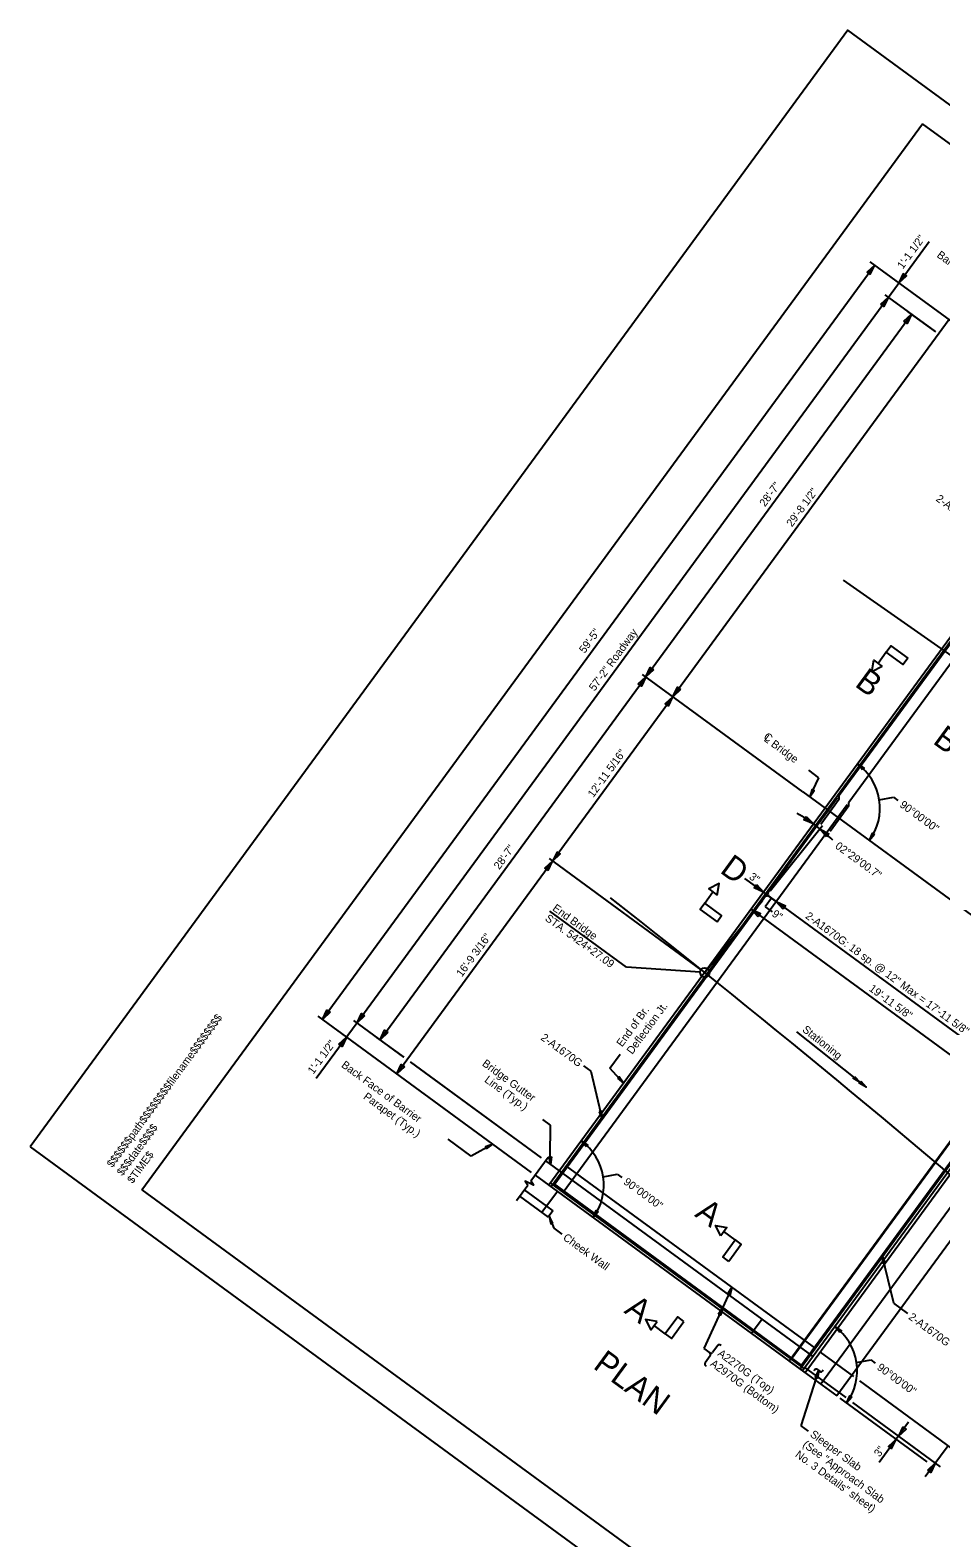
# Model space of a CAD drawing. Extents: x 1970731 to 1970899, y 796145 to 796301.
# Drawn here: x 1970731.3 to 1970789.2, y 796205.4 to 796301.3 of the extents above; entities that cross this region are included whole.
import ezdxf

# ---------------------------------------------------------------- set-up
doc = ezdxf.new("R2010")
doc.units = 0
for name, color, linetype in [('BR_AUTO DIMENSION', 7, 'Continuous'), ('BR_BORDER LINES', 7, 'Continuous'), ('BR_CENTER LINES', 7, 'Continuous'), ('BR_CONCRETE', 7, 'Continuous'), ('BR_DETAILS', 7, 'Continuous'), ('BR_REBAR', 7, 'Continuous'), ('BR_TABLE LINES', 7, 'Continuous'), ('BR_TEXT', 7, 'Continuous'), ('Level 31', 7, 'Continuous'), ('RD_SHT_ID', 7, 'Continuous')]:
    doc.layers.add(name, color=color, linetype=linetype)

msp = doc.modelspace()

# ---------------------------------------------------------------- linework, layer by layer
at = {"layer": 'BR_AUTO DIMENSION'}
for p, q in [((1970785.817, 796284.313), (1970788.404, 796287.847)), ((1970784.949, 796286.342), (1970749.841, 796238.39)), ((1970798.342, 796276.537), (1970784.666, 796286.55)), ((1970785.817, 796284.313), (1970752.038, 796238.176)), ((1970788.808, 796282.122), (1970785.615, 796284.46)), ((1970770.395, 796260.17), (1970787.284, 796283.238)), ((1970788.834, 796282.104), (1970787.082, 796283.386)), ((1970789.674, 796282.883), (1970754.567, 796234.93)), ((1970780.373, 796252.864), (1970770.193, 796260.318)), ((1970753.505, 796237.102), (1970770.395, 796260.17)), ((1970781.403, 796253.756), (1970780.759, 796254.228)), ((1970780.819, 796252.536), (1970781.403, 796253.756)), ((1970785.237, 796252.356), (1970786.133, 796252.526)), ((1970786.133, 796252.526), (1970786.423, 796252.314)), ((1970778.301, 796246.565), (1970781.634, 796250.726)), ((1970764.249, 796248.619), (1970773.902, 796241.552)), ((1970776.671, 796247.359), (1970777.878, 796246.475)), ((1970777.368, 796245.401), (1970777.816, 796245.96)), ((1970777.502, 796246.751), (1970778.147, 796246.279)), ((1970778.384, 796246.105), (1970777.978, 796245.551)), ((1970778.685, 796245.885), (1970778.147, 796246.279)), ((1970778.147, 796246.279), (1970778.685, 796245.885)), ((1970778.685, 796245.885), (1970795.08, 796233.881)), ((1970769.163, 796241.706), (1970764.286, 796245.277)), ((1970774.144, 796241.375), (1970777.099, 796245.065)), ((1970777.089, 796245.398), (1970793.2, 796233.603)), ((1970777.978, 796245.551), (1970778.427, 796245.222)), ((1970773.844, 796241.395), (1970769.163, 796241.706)), ((1970752.038, 796238.176), (1970749.45, 796234.641)), ((1970763.131, 796228.66), (1970749.558, 796238.598)), ((1970755.011, 796235.999), (1970751.836, 796238.324)), ((1970755.027, 796235.987), (1970753.304, 796237.249)), ((1970779.976, 796237.607), (1970784.401, 796234.085)), ((1970763.763, 796229.591), (1970755.431, 796235.692)), ((1970763.763, 796229.591), (1970755.459, 796235.671)), ((1970766.431, 796235.44), (1970766.897, 796235.099)), ((1970768.114, 796235.286), (1970768.773, 796236.186)), ((1970766.897, 796235.099), (1970767.627, 796232.05)), ((1970768.985, 796234.329), (1970768.114, 796235.286)), ((1970764.346, 796231.676), (1970763.853, 796232.037)), ((1970764.32, 796229.662), (1970764.346, 796231.676)), ((1970759.302, 796229.701), (1970757.833, 796230.776)), ((1970760.668, 796230.463), (1970759.302, 796229.701)), ((1970767.683, 796228.38), (1970768.579, 796228.55)), ((1970768.579, 796228.55), (1970768.869, 796228.338)), ((1970764.25, 796225.886), (1970764.559, 796225.109)), ((1970764.559, 796225.109), (1970765.053, 796224.748)), ((1970786.154, 796220.358), (1970785.425, 796223.407)), ((1970775.872, 796221.345), (1970774.084, 796217.461)), ((1970787.054, 796219.7), (1970786.154, 796220.358)), ((1970774.084, 796217.461), (1970774.463, 796217.184)), ((1970774.965, 796217.659), (1970774.637, 796217.211)), ((1970775.186, 796217.652), (1970775.14, 796217.686)), ((1970781.478, 796217.241), (1970783.596, 796215.691)), ((1970774.49, 796217.009), (1970774.162, 796216.561)), ((1970774.189, 796216.386), (1970774.235, 796216.353)), ((1970780.464, 796216.279), (1970783.101, 796214.349)), ((1970783.793, 796216.585), (1970784.69, 796216.755)), ((1970784.69, 796216.755), (1970784.979, 796216.543)), ((1970780.264, 796212.555), (1970781.385, 796216.076)), ((1970783.969, 796215.417), (1970789.812, 796211.14)), ((1970782.737, 796214.305), (1970788.261, 796210.261)), ((1970782.737, 796214.305), (1970788.261, 796210.261)), ((1970783.541, 796214.026), (1970789.11, 796209.949)), ((1970780.739, 796212.208), (1970780.264, 796212.555)), ((1970787.104, 796212.78), (1970785.226, 796210.215)), ((1970789.61, 796211.287), (1970788.161, 796209.308))]:
    msp.add_line(p, q, dxfattribs=at)
for points in [[(1970784.666, 796285.744), (1970784.949, 796286.342), (1970784.464, 796285.892)], [(1970786.764, 796285.819), (1970786.481, 796285.22), (1970786.966, 796285.671)], [(1970785.332, 796283.862), (1970785.817, 796284.313), (1970785.533, 796283.714)], [(1970786.799, 796282.788), (1970787.284, 796283.238), (1970787.001, 796282.64)], [(1970770.88, 796260.621), (1970770.395, 796260.17), (1970770.678, 796260.768)], [(1970769.91, 796259.719), (1970770.395, 796260.17), (1970770.112, 796259.572)], [(1970772.605, 796259.357), (1970772.12, 796258.906), (1970772.404, 796259.505)], [(1970771.837, 796258.308), (1970772.12, 796258.906), (1970771.636, 796258.456)], [(1970784.175, 796254.257), (1970783.852, 796254.635), (1970784.272, 796254.369)], [(1970780.967, 796253.019), (1970780.819, 796252.536), (1970781.102, 796252.954)], [(1970780.593, 796251.289), (1970781.057, 796250.817), (1970780.451, 796251.083)], [(1970781.874, 796249.993), (1970781.459, 796250.508), (1970782.036, 796250.184)], [(1970784.929, 796250.143), (1970784.605, 796249.766), (1970784.804, 796250.221)], [(1970764.753, 796249.055), (1970764.47, 796248.457), (1970764.955, 796248.908)], [(1970764.187, 796247.859), (1970764.47, 796248.457), (1970763.985, 796248.006)], [(1970777.427, 796246.96), (1970777.878, 796246.475), (1970777.28, 796246.759)], [(1970779.136, 796245.4), (1970778.685, 796245.885), (1970779.283, 796245.602)], [(1970777.54, 796244.913), (1970777.089, 796245.398), (1970777.688, 796245.115)], [(1970750.326, 796238.841), (1970749.841, 796238.39), (1970750.124, 796238.988)], [(1970752.523, 796238.626), (1970752.038, 796238.176), (1970752.321, 796238.774)], [(1970750.889, 796236.818), (1970751.373, 796237.268), (1970751.09, 796236.67)], [(1970753.99, 796237.552), (1970753.505, 796237.102), (1970753.788, 796237.7)], [(1970755.051, 796235.381), (1970754.567, 796234.93), (1970754.85, 796235.529)], [(1970768.593, 796234.649), (1970768.985, 796234.329), (1970768.704, 796234.75)], [(1970783.666, 796234.766), (1970784.01, 796234.396), (1970783.572, 796234.649)], [(1970784.056, 796234.456), (1970784.401, 796234.085), (1970783.963, 796234.338)], [(1970767.437, 796232.519), (1970767.627, 796232.05), (1970767.583, 796232.554)], [(1970766.621, 796230.281), (1970766.298, 796230.659), (1970766.718, 796230.392)], [(1970760.268, 796230.154), (1970760.668, 796230.463), (1970760.195, 796230.285)], [(1970764.396, 796229.664), (1970764.338, 796229.171), (1970764.248, 796229.66)], [(1970764.495, 796225.444), (1970764.25, 796225.886), (1970764.355, 796225.392)], [(1970767.375, 796226.167), (1970767.051, 796225.79), (1970767.25, 796226.245)], [(1970785.614, 796222.938), (1970785.425, 796223.407), (1970785.468, 796222.903)], [(1970775.595, 796220.923), (1970775.872, 796221.345), (1970775.731, 796220.86)], [(1970775.008, 796219.648), (1970775.285, 796220.071), (1970775.144, 796219.585)], [(1970782.731, 796218.486), (1970782.408, 796218.864), (1970782.828, 796218.597)], [(1970781.162, 796215.622), (1970781.385, 796216.076), (1970781.305, 796215.577)], [(1970783.485, 796214.372), (1970783.161, 796213.995), (1970783.361, 796214.45)], [(1970786.738, 796212.492), (1970786.455, 796211.893), (1970786.94, 796212.344)], [(1970786.024, 796211.093), (1970786.307, 796211.692), (1970785.822, 796211.241)], [(1970788.313, 796209.727), (1970788.798, 796210.178), (1970788.515, 796209.58)]]:
    msp.add_lwpolyline(points, close=True, dxfattribs=at)
for centre, radius in [((1970778.08, 796246.328), 0.0915), ((1970774.144, 796241.375), 0.3)]:
    msp.add_circle(centre, radius, dxfattribs=at)
for centre, radius, start, end in [((1970781.794, 796251.824), 3.484, 323.79058, 53.79058), ((1970774.144, 796241.375), 11.703, 45.98111, 59.88175), ((1970764.24, 796227.848), 3.484, 323.79058, 53.79058), ((1970780.35, 796216.053), 3.484, 323.79058, 53.79058), ((1970774.537, 796217.285), 0.125, 233.79058, 323.79058), ((1970774.389, 796217.083), 0.125, 323.79058, 53.79058), ((1970775.066, 796217.585), 0.125, 53.79058, 143.79058), ((1970774.263, 796216.487), 0.125, 143.79058, 233.79058)]:
    msp.add_arc(centre, radius, start, end, dxfattribs=at)
at = {"layer": 'BR_BORDER LINES'}
for p, q in [((1970738.359, 796227.562), (1970787.981, 796295.338)), ((1970896.636, 796215.787), (1970787.981, 796295.338)), ((1970738.359, 796227.562), (1970847.014, 796148.01))]:
    msp.add_line(p, q, dxfattribs=at)
at = {"layer": 'BR_CENTER LINES'}
for p, q in [((1970782.944, 796266.315), (1970822.233, 796238.791)), ((1970780.381, 796252.859), (1970800.291, 796238.281))]:
    msp.add_line(p, q, dxfattribs=at)
msp.add_arc((1970326.539, 795682.531), 716, 48.768651, 51.918253, dxfattribs=at)
at = {"layer": 'BR_CONCRETE'}
for p, q in [((1970799.34, 796275.789), (1970764.24, 796227.848)), ((1970814.843, 796264.928), (1970779.51, 796216.668)), ((1970815.696, 796264.33), (1970780.35, 796216.053)), ((1970816.012, 796264.409), (1970780.518, 796215.93)), ((1970817.021, 796263.671), (1970781.527, 796215.191)), ((1970818.029, 796262.932), (1970782.536, 796214.453)), ((1970764.02, 796229.403), (1970765.443, 796228.362)), ((1970763.356, 796228.495), (1970764.778, 796227.454)), ((1970765.443, 796228.362), (1970781.015, 796216.961)), ((1970762.371, 796227.151), (1970764.197, 796225.814)), ((1970762.666, 796227.554), (1970764.089, 796226.513)), ((1970764.778, 796227.454), (1970763.793, 796226.109)), ((1970764.778, 796227.454), (1970780.35, 796216.053)), ((1970764.089, 796226.513), (1970764.492, 796226.217)), ((1970764.492, 796226.217), (1970764.197, 796225.814)), ((1970777.787, 796219.324), (1970777.123, 796218.416)), ((1970779.51, 796216.668), (1970782.536, 796214.453))]:
    msp.add_line(p, q, dxfattribs=at)
at = {"layer": 'BR_DETAILS'}
for p, q in [((1970763.079, 796228.118), (1970764.188, 796229.632)), ((1970762.174, 796226.881), (1970762.887, 796227.855)), ((1970781.301, 796216.135), (1970781.469, 796216.017)), ((1970781.63, 796216.058), (1970781.663, 796216.118)), ((1970781.094, 796216.046), (1970781.116, 796216.093))]:
    msp.add_line(p, q, dxfattribs=at)
msp.add_lwpolyline([(1970763.079, 796228.118), (1970763.249, 796227.86), (1970762.718, 796228.114), (1970762.887, 796227.855)], dxfattribs=at)
for centre, radius, start, end in [((1970781.224, 796216.049), 0.116, 48.24619, 158.04507), ((1970781.534, 796216.095), 0.103, 230.69104, 338.97662)]:
    msp.add_arc(centre, radius, start, end, dxfattribs=at)
at = {"layer": 'BR_REBAR'}
for p, q in [((1970799.446, 796275.511), (1970782.689, 796252.623)), ((1970800.061, 796275.081), (1970783.294, 796252.18)), ((1970782.696, 796252.403), (1970782.689, 796252.623)), ((1970782.586, 796252.483), (1970764.54, 796227.835)), ((1970783.192, 796252.04), (1970765.145, 796227.392)), ((1970782.696, 796252.403), (1970781.515, 796250.789)), ((1970783.301, 796251.96), (1970782.12, 796250.346)), ((1970783.301, 796251.96), (1970783.294, 796252.18)), ((1970797.688, 796241.427), (1970779.642, 796216.778)), ((1970798.293, 796240.984), (1970780.247, 796216.335)), ((1970765.335, 796229.061), (1970781.176, 796217.462)), ((1970764.522, 796227.951), (1970780.364, 796216.353))]:
    msp.add_line(p, q, dxfattribs=at)
at = {"layer": 'BR_TABLE LINES'}
for p, q in [((1970785.684, 796261.741), (1970785.159, 796261.024)), ((1970774.141, 796245.776), (1970774.666, 796246.493)), ((1970776.072, 796224.375), (1970775.355, 796224.9)), ((1970771.634, 796218.398), (1970770.917, 796218.923))]:
    msp.add_line(p, q, dxfattribs=at)
for points in [[(1970787.049, 796261.348), (1970786.76, 796260.953), (1970785.684, 796261.741), (1970785.973, 796262.135)], [(1970785.428, 796260.827), (1970784.766, 796260.486), (1970784.89, 796261.22)], [(1970774.935, 796246.296), (1970775.06, 796247.031), (1970774.397, 796246.69)], [(1970774.928, 796244.594), (1970775.217, 796244.989), (1970774.141, 796245.776), (1970773.852, 796245.382)], [(1970775.158, 796224.631), (1970774.817, 796225.294), (1970775.552, 796225.169)], [(1970775.679, 796223.01), (1970775.284, 796223.299), (1970776.072, 796224.375), (1970776.467, 796224.086)], [(1970771.114, 796219.192), (1970770.379, 796219.317), (1970770.72, 796218.654)], [(1970772.816, 796219.185), (1970772.422, 796219.474), (1970771.634, 796218.398), (1970772.028, 796218.109)]]:
    msp.add_lwpolyline(points, close=True, dxfattribs=at)
at = {"layer": 'Level 31'}
for p, q in [((1970799.474, 796275.691), (1970764.375, 796227.749)), ((1970815.562, 796264.429), (1970780.216, 796216.151)), ((1970764.339, 796227.982), (1970780.449, 796216.187))]:
    msp.add_line(p, q, dxfattribs=at)
msp.add_lwpolyline([(1970731.261, 796230.28), (1970847.449, 796145.214), (1970899.434, 796216.218), (1970783.245, 796301.284)], close=True, dxfattribs=at)

# ---------------------------------------------------------------- texts
at = {"layer": 'BR_AUTO DIMENSION'}
for s, rotation, p in [('1\'-1 1/2"', 53.79058, (1970786.732, 796286.054)), ('28\'-7"', 53.79058, (1970777.975, 796270.947)), ('29\'-8 1/2"', 53.79058, (1970779.689, 796269.666)), ('59\'-5"', 53.79058, (1970766.51, 796261.625)), ('57\'-2" Roadway', 53.79058, (1970767.14, 796259.227)), ('C', 323.79058, (1970777.837, 796256.269)), ('12\'-11 5/16"', 53.79058, (1970767.056, 796252.457)), ('28\'-7"', 53.79058, (1970761.086, 796247.879)), ('3"', 323.79058, (1970776.92, 796247.366)), ('9"', 323.79058, (1970778.365, 796245.005)), ('2-A1670G: 18 sp. @ 12" Max = 17\'-11 5/8"', 323.79058, (1970780.498, 796244.867)), ('16\'-9 3/16"', 53.79058, (1970758.705, 796241.05)), ('19\'-11 5/8"', 323.79058, (1970784.537, 796240.255)), ('1\'-1 1/2"', 53.79058, (1970749.255, 796234.866)), ('3"', 53.79058, (1970785.255, 796210.536))]:
    msp.add_text(s, height=0.5, rotation=rotation, dxfattribs=at).set_placement(p)
at = {"layer": 'BR_TEXT'}
for s, height, rotation, p in [('Barrier Parapet (2)" Sheets (Typ.) ', 0.49995, 323.79058, (1970788.851, 796286.896)), ('2-A1670G', 0.4999, 323.79058, (1970788.798, 796271.397)), ('B', 1.5, 323.79058, (1970783.614, 796259.615)), ('L Bridge', 0.5, 323.79058, (1970777.859, 796256.128)), ('B', 1.5, 323.79058, (1970788.575, 796255.983)), ('90%%d00\'00"', 0.5, 323.79058, (1970786.493, 796251.942)), ('02%%d29\'00.7"', 0.5, 323.79058, (1970782.39, 796249.318)), ('D', 1.5, 323.79058, (1970775.04, 796247.767)), ('STA. 5424+27.09', 0.5, 323.79058, (1970763.948, 796244.719)), ('End Bridge', 0.5, 323.79058, (1970764.421, 796245.365)), ('Deflection Jt.', 0.49995, 53.79058, (1970769.535, 796236.132)), ('End of Br.', 0.4999, 53.79058, (1970768.889, 796236.605)), ('2-A1670G', 0.4999, 323.79058, (1970763.673, 796237.138)), ('Stationing', 0.4999, 321.48295, (1970780.303, 796237.666)), ('Back Face of Barrier', 0.49995, 323.79058, (1970750.999, 796235.4)), ('Bridge Gutter ', 0.49995, 323.79058, (1970759.95, 796235.492)), ('Line (Typ.)', 0.49995, 323.79058, (1970760.097, 796234.455)), ('Parapet (Typ.)', 0.49995, 323.79058, (1970752.397, 796233.385)), ('90%%d00\'00"', 0.5, 323.79058, (1970768.939, 796227.966)), ('A', 1.5, 323.79058, (1970773.447, 796225.91)), ('Cheek Wall', 0.4999, 323.79058, (1970765.089, 796224.426)), ('A', 1.5, 323.79058, (1970768.958, 796219.779)), ('2-A1670G', 0.4999, 323.79058, (1970787.054, 796219.377)), ('PLAN', 1.5, 323.79058, (1970766.982, 796216.253)), ('A2270G (Top)', 0.49995, 323.79058, (1970774.92, 796217.057)), ('A2970G (Bottom) ', 0.49995, 323.79058, (1970774.447, 796216.412)), ('90%%d00\'00"', 0.5, 323.79058, (1970785.049, 796216.171)), ('(See "Approach Slab', 0.49995, 323.79058, (1970780.321, 796211.271)), ('Sleeper Slab ', 0.49995, 323.79058, (1970780.793, 796211.917)), ('No. 3 Details" sheet)', 0.49995, 323.79058, (1970779.848, 796210.626))]:
    msp.add_text(s, height=height, rotation=rotation, dxfattribs=at).set_placement(p)
at = {"layer": 'RD_SHT_ID'}
for s, height, p in [('$$$$$$path$$$$$$$$filename$$$$$$$$', 0.49387, (1970736.488, 796228.931)), ('$$$date$$$$', 0.49387, (1970737.121, 796228.403)), ('$TIME$', 0.4939, (1970737.781, 796227.92))]:
    msp.add_text(s, height=height, rotation=53.79058, dxfattribs=at).set_placement(p)

doc.saveas('drawing.dxf')
